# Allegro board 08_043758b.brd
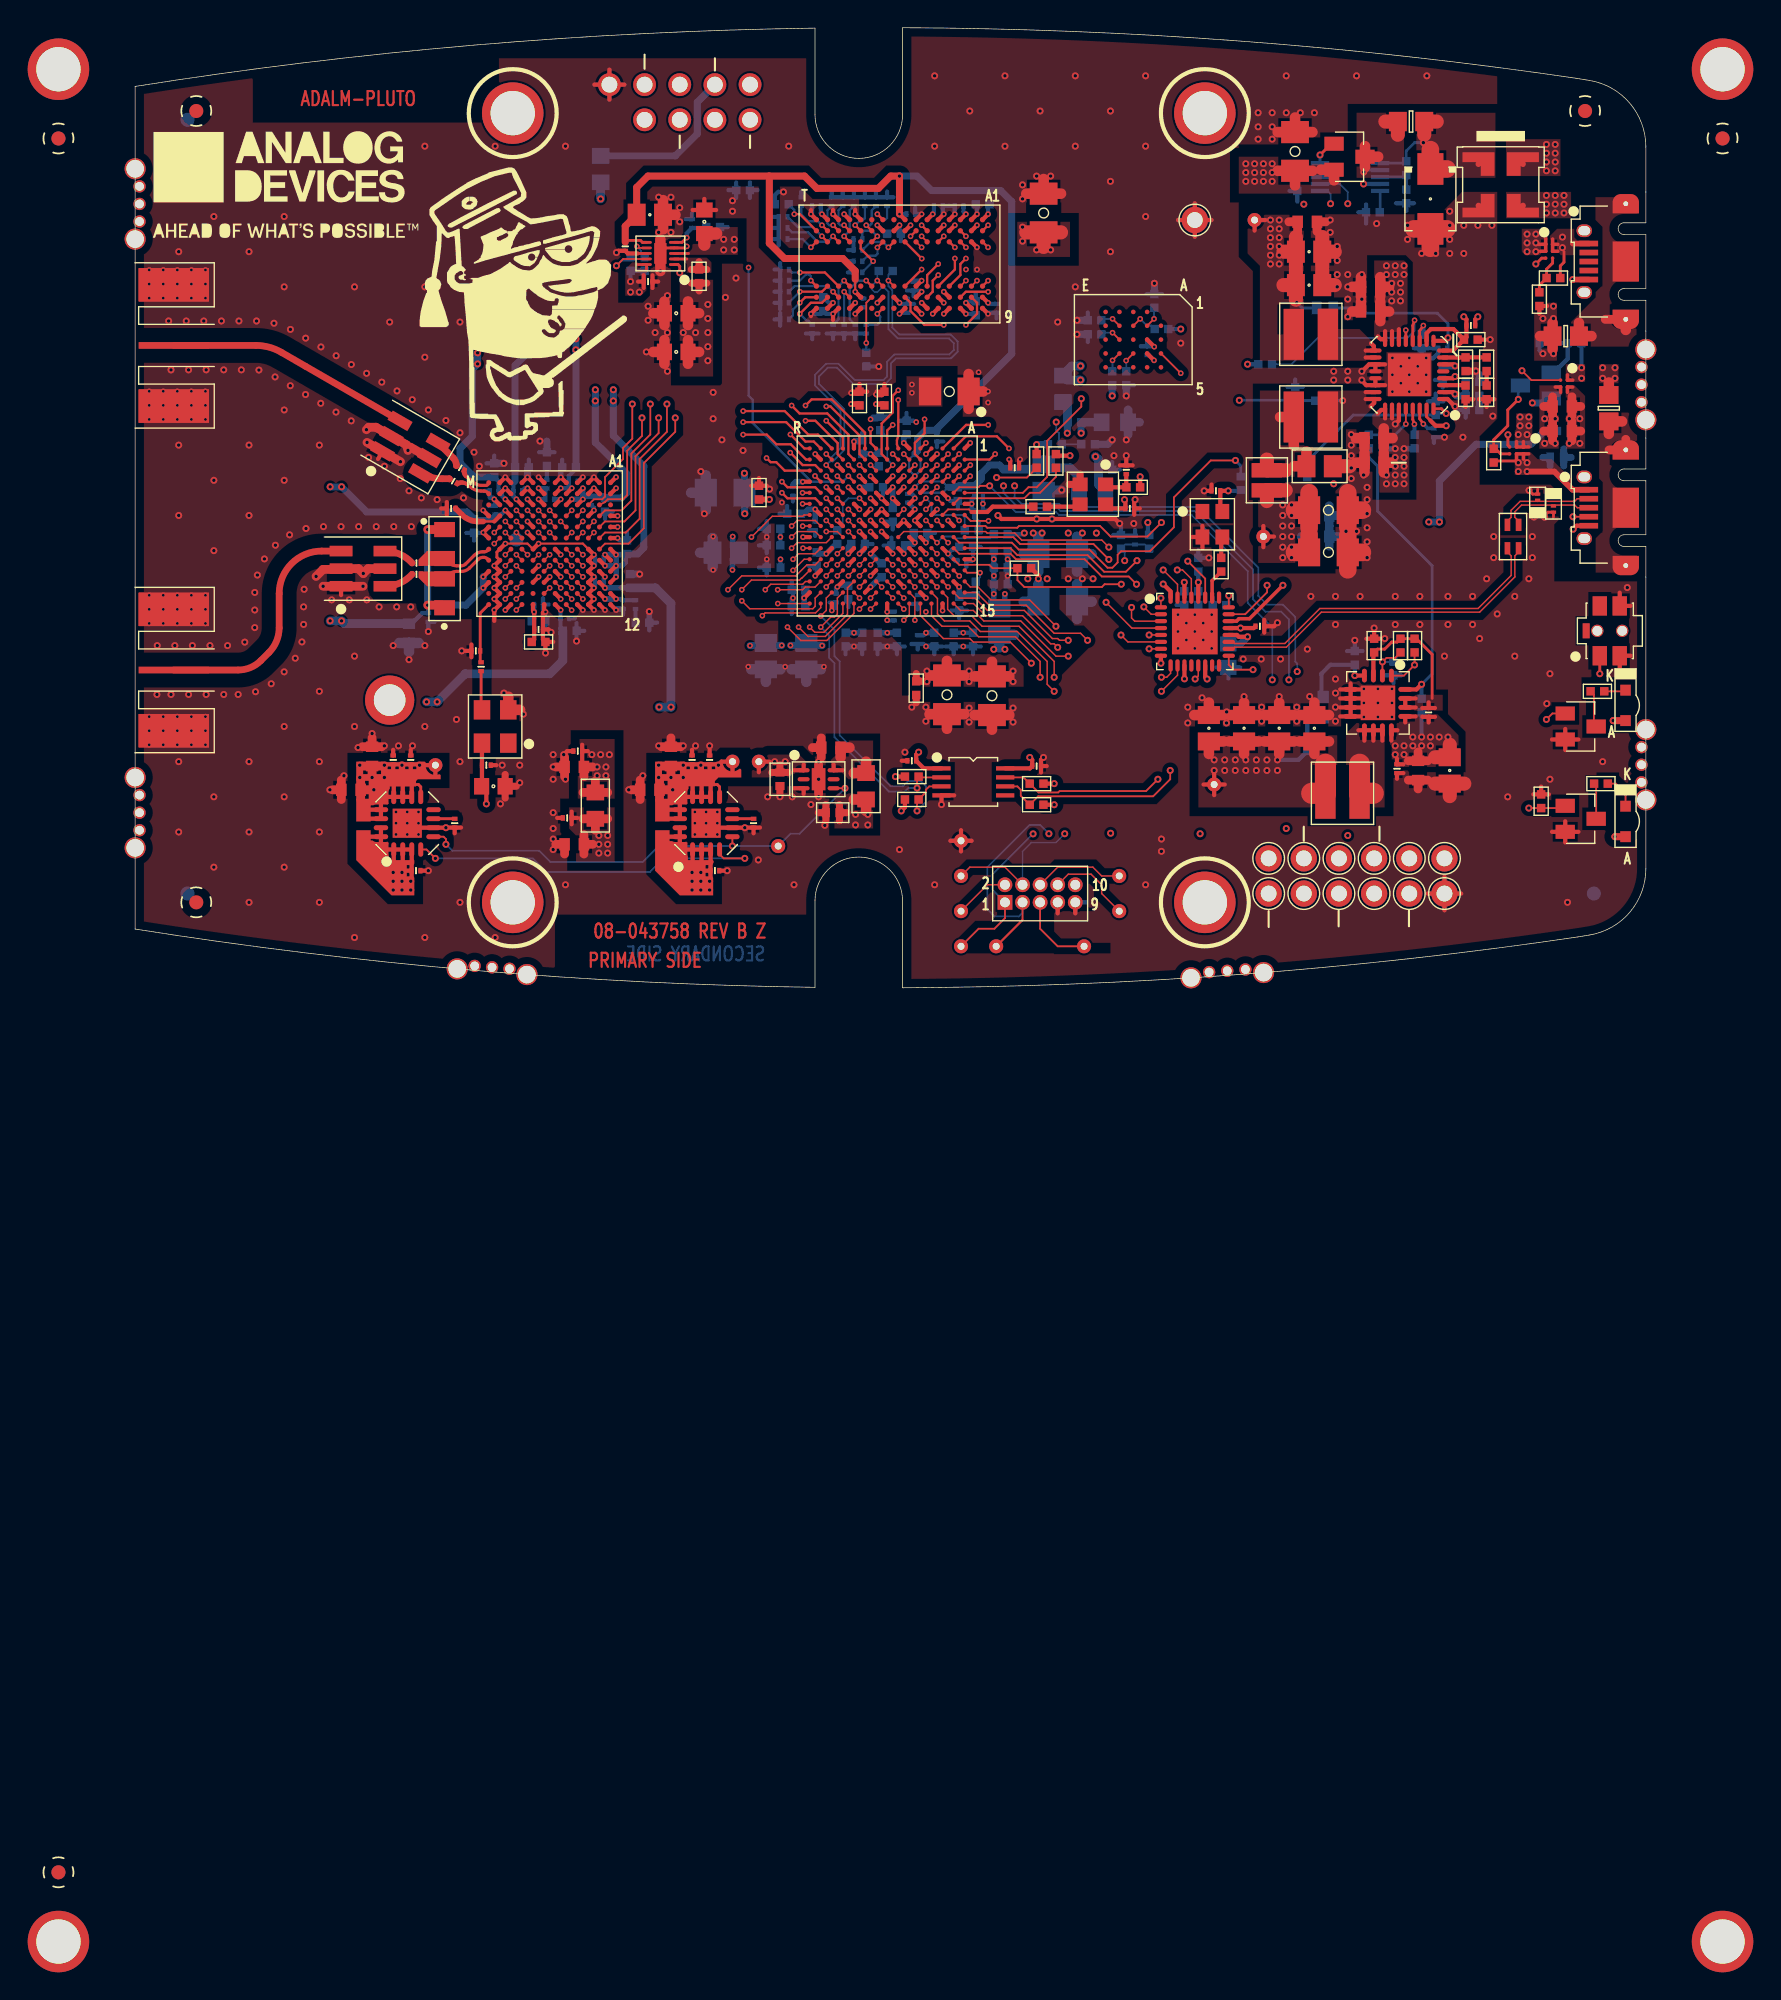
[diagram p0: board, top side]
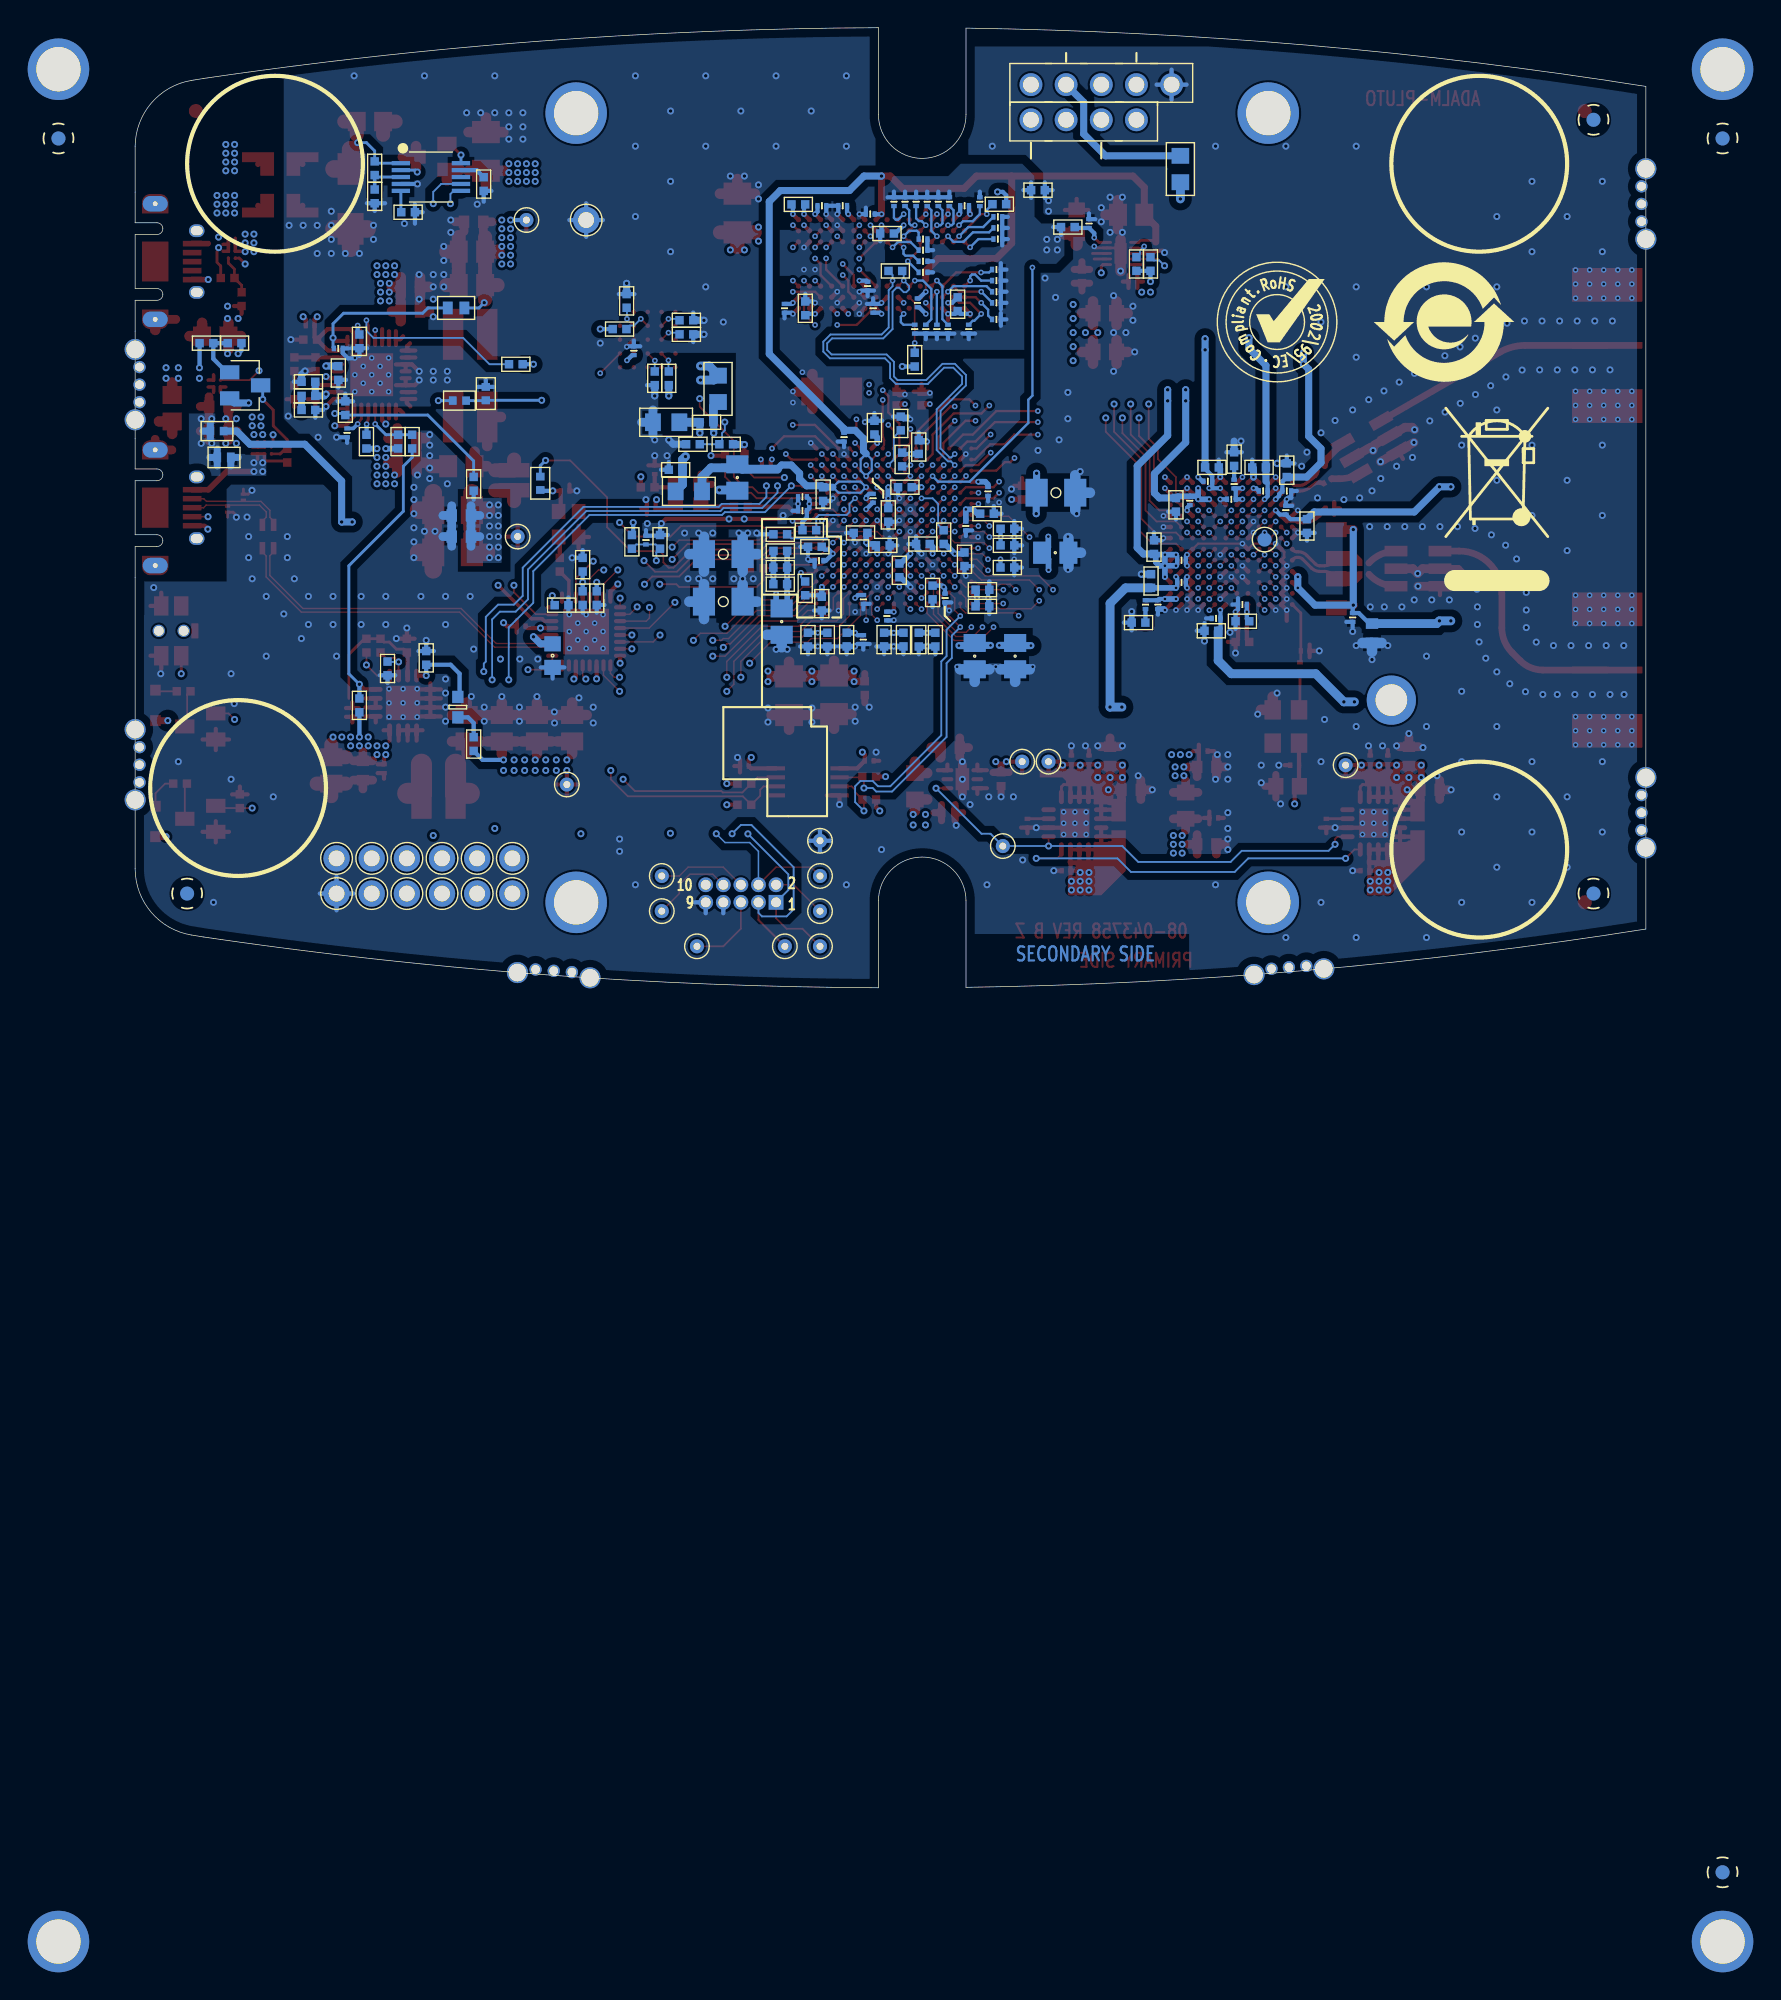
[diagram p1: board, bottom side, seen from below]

Outline 109.14 x 69.34 mm; copper layers: TOP, L2_GND, L3_PWR, L4_GND, L5_SIG, L6_SIG, L7_GND, L8_PWR, L9_GND, BOTTOM. Coordinates in mm from the lower left corner of the outline.
Outline path: 0,65.1 arc(24.48,68.08) 49.11,69.31 49.11,63.06 arc(52.28,59.9) 55.44,63.06 55.44,69.34 arc(79.87,68.37) 104.18,65.67 105.05,65.53 arc(107.98,63.88) 109.14,60.73 109.14,57.47 109.14,55.25 107.56,55.25 arc(107.26,55.12) 107.14,54.82 arc(107.26,54.52) 107.56,54.4 109.14,54.4 109.14,50.5 107.56,50.5 arc(107.26,50.37) 107.14,50.07 arc(107.26,49.77) 107.56,49.65 109.14,49.65 109.14,37.47 107.56,37.47 arc(107.26,37.34) 107.14,37.04 arc(107.26,36.74) 107.56,36.62 109.14,36.62 109.14,32.72 107.56,32.72 arc(107.26,32.59) 107.14,32.29 arc(107.26,31.99) 107.56,31.87 109.14,31.87 109.14,29.65 109.14,8.61 arc(107.98,5.45) 105.05,3.81 104.18,3.67 arc(79.87,0.97) 55.44,0 55.44,6.28 arc(52.28,9.44) 49.11,6.28 49.11,0.03 arc(24.48,1.26) 0,4.24 0,65.1

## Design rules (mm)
constraint set DEFAULT: min track width 0.127
net group DDR3_CK: nets DDR3_CK_N DDR3_CK_P
net group DDR3_DQS0: nets DDR3_DQS0_N DDR3_DQS0_P
net group DDR3_DQS1: nets DDR3_DQS1_N DDR3_DQS1_P
net group DP1: nets UNNAMED_9_CHOKE4P_I327_N2 UNNAMED_9_CHOKE4P_I327_N3
net group RX1A: nets RX1A_N RX1A_P
net group TX1A: nets TX1A_N TX1A_P
net group UART: nets UART_RX UART_TX
net group USB_OTG: nets USB_OTG_N USB_OTG_P
net group CTRL_IN: nets CTRL_IN0 CTRL_IN1 CTRL_IN2 CTRL_IN3
net group CTRL_OUT: nets IO_L08_34_CTRL_OUT0 IO_L08_34_CTRL_OUT1 IO_L13_34_CTRL_OUT2 IO_L13_34_CTRL_OUT3 IO_L21_34_CTRL_OUT4 IO_L21_34_CTRL_OUT5 IO_L22_34_CTRL_OUT6 IO_L22_34_CTRL_OUT7
net group JTAG: nets JTAG_TCK JTAG_TDI JTAG_TDO JTAG_TMS
net group PWR: nets VCCPLL VDD33_USB VDDA1P1_RX_VCO VTTVREF
net group QSPI: nets PS_MIO01_500_QSPI0_SS_B PS_MIO02_500_QSPI0_IO0 PS_MIO03_500_QSPI0_IO1 PS_MIO04_500_QSPI0_IO2 PS_MIO05_500_QSPI0_IO3 PS_MIO06_500_QSPI0_SCLK
net group RF: nets UNNAMED_7_CAP_I39_N2 UNNAMED_7_CAP_I40_N2 UNNAMED_7_CAP_I51_N1 UNNAMED_7_CAP_I52_N1 UNNAMED_7_CNBNC5P_I57_CNTR UNNAMED_7_CNBNC5P_I58_CNTR
net group RX: nets IO_L01_34_RX_D0 IO_L01_34_RX_D1 IO_L02_34_RX_D2 IO_L02_34_RX_D3 IO_L03_34_RX_D4 IO_L03_34_RX_D5 IO_L04_34_RX_D6 IO_L04_34_RX_D7 IO_L05_34_RX_D8 IO_L05_34_RX_D9 IO_L06_34_RX_D10 IO_L06_34_RX_D11 IO_L07_34_RX_FRAME IO_L12_MRCC_34_DATA_CLK
net group SPI: nets IO_L23_35_SPI_CLK IO_L23_35_SPI_ENB IO_L24_35_SPI_DI IO_L24_35_SPI_DO
net group TX: nets IO_L01_34_FB_CLK IO_L09_34_TX_FRAME IO_L15_34_TX_D0 IO_L15_34_TX_D1 IO_L16_34_TX_D2 IO_L16_34_TX_D3 IO_L17_34_TX_D4 IO_L17_34_TX_D5 IO_L18_34_TX_D6 IO_L18_34_TX_D7 IO_L19_34_TX_D8 IO_L19_34_TX_D9 IO_L20_34_TX_D10 IO_L20_34_TX_D11
net group USB_ULPI: nets PS_MIO28_501_USB0_D4 PS_MIO29_501_USB0_DIR PS_MIO30_501_USB0_STP PS_MIO31_501_USB0_NXT PS_MIO32_501_USB0_D0 PS_MIO33_501_USB0_D1 PS_MIO34_501_USB0_D2 PS_MIO35_501_USB0_D3 PS_MIO36_501_USB0_CLK PS_MIO37_501_USB0_D5 PS_MIO38_501_USB0_D6 PS_MIO39_501_USB0_D7

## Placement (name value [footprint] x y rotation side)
AD9361_CLKOUT  TESTPAD  [TPSMC40]  27.55 32.37 180 bottom
ADC  613 001 111 21  [CNHDR1X1H344]  44.42 65.22 180 bottom
C1  0.1uF  [C0201]  20.29 8.46 0 top
C2  0.01uF  [C0201]  23.09 11.88 270 top
C3  10uF  [C0603]  15.59 14.3 180 top
C4  10uF  [C0603]  17.12 16.71 90 top
C5  0.1uF  [C0201]  18.64 16.46 90 top
C6  0.1uF  [C0201]  19.91 16.46 90 top
C7  0.1uF  [C0201]  93.83 40.08 90 bottom
C8  0.1uF  [C0201]  91.16 15.82 270 top
C9  10uF  [C0603]  92.68 15.69 270 top
C10  0.1uF  [C0201]  41.88 8.46 0 top
C11  47uF  [C0805H60]  94.97 15.69 270 top
C12  0.01uF  [C0201]  44.68 11.88 270 top
C13  0.1uF  [C0201#2]  89.51 24.71 90 top
C14  10uF  [C0603]  38.71 16.71 90 top
C15  10uF  [C0603]  37.18 14.3 180 top
C16  0.1uF  [C0201]  40.23 16.46 90 top
C17  47uF  [C0805H60]  82.65 18.74 90 top
C18  0.1uF  [C0201]  41.5 16.46 90 top
C19  47uF  [C0805H60]  77.57 18.74 90 top
C20  47uF  [C0805H60]  80.11 18.74 90 top
C21  47uF  [C0805H60]  85.19 18.74 90 top
C22  10uF  [C0603]  31.72 10.36 180 top
C23  0.01uF  [C0201]  31.65 36.58 0 bottom
C24  0.01uF  [C0201]  25.94 35.88 180 bottom
C25  0.1uF  [C0201]  31.21 12.27 180 top
C26  0.01uF  [C0201]  31.05 26.68 0 bottom
C27  0.01uF  [C0201]  33.54 30.88 180 bottom
C28  1uF  [C0402]  31.35 37.58 180 bottom
C29  1uF  [C0402]  25.94 37.38 90 bottom
C30  1uF  [C0402]  31.39 25.78 0 bottom
C31  1uF  [C0402]  35.53 31.82 90 bottom
C32  10uF  [C0603]  31.72 15.95 180 top
C33  0.1uF  [C0201]  31.98 17.09 180 top
C34  1uF  [C0402]  27.94 37.58 0 bottom
C35  1uF  [C0402]  35.75 29.38 90 bottom
C36  1uF  [C0402]  24.48 33.35 270 bottom
C37  1uF  [C0402]  33.95 34.88 270 bottom
C38  1uF  [C0402]  29.15 26.47 0 bottom
C39  0.01uF  [C0201]  27.64 35.88 0 bottom
C40  0.01uF  [C0201]  33.54 29.28 180 bottom
C41  0.01uF  [C0201]  26.01 34.49 90 bottom
C42  0.01uF  [C0201]  32.95 35.18 270 bottom
C43  0.01uF  [C0201]  29.14 25.88 0 top
C44  0.01uF  [C0201]  29.15 27.68 0 bottom
C45  1uF  [C0402]  29.14 24.98 0 top
C46  0.1uF  [C0201]  71.85 34.62 0 top
C47  0.1uF  [C0201]  72.24 32.33 90 bottom
C48  0.1uF  [C0201]  73.11 46.01 90 bottom
C49  100uF  [C1206H71]  66.65 31.32 0 bottom
C50  4.7uF  [C0402]  62.53 31.55 0 bottom
C51  0.47uF  [C0402]  47.6 34.24 180 bottom
C52  0.1uF  [C0201]  60.93 35.45 0 bottom
C53  0.01uF  [C0201]  60.93 34.45 0 bottom
C54  100uF  [C1206H71]  58.82 43.06 0 top
C55  4.7uF  [C0402]  55.73 40.45 90 bottom
C56  0.47uF  [C0402]  45.07 35.76 90 top
C57  0.47uF  [C0402]  54.13 42.55 90 top
C58  0.47uF  [C0402]  52.33 42.55 90 top
C59  0.47uF  [C0402]  52.53 39.05 90 bottom
C60  0.1uF  [C0201]  63.54 37.56 0 top
C61  0.01uF  [C0201]  47.52 35.85 270 bottom
C62  0.01uF  [C0201]  37.06 51 180 top
C63  0.01uF  [C0201]  56.03 55.88 180 bottom
C64  100uF  [C1206H71]  61.9 21.09 270 top
C65  47uF  [C0805H60]  48.49 23.95 270 bottom
C66  4.7uF  [C0402]  53.93 30.15 270 bottom
C67  4.7uF  [C0402]  52.53 25.14 270 bottom
C68  0.47uF  [C0402]  56.43 21.64 270 top
C69  0.47uF  [C0402]  60.03 31.85 0 bottom
C70  0.47uF  [C0402]  54.73 34.15 270 bottom
C71  100uF  [C1206H71]  58.65 21.16 270 top
C72  0.47uF  [C0402]  52.23 32.05 0 bottom
C73  4.7uF  [C0402]  53.53 36.15 0 bottom
C74  0.47uF  [C0402]  55.13 31.95 180 bottom
C75  0.47uF  [C0402]  56.73 32.85 0 bottom
C76  100uF  [C1206H71]  42.62 35.75 180 bottom
C77  47uF  [C0805H60]  42.67 31.42 180 bottom
C78  4.7uF  [C0402]  46.12 31.95 180 bottom
C79  10uF  [C0603#2]  41.12 55.32 90 top
C80  0.01uF  [C0201]  40.23 55.19 90 bottom
C81  0.22UF  [C0805]  37.18 55.83 0 top
C82  10uF  [C0603#2]  39.09 45.92 180 top
C83  10uF  [C0603#2]  39.09 48.71 180 top
C84  0.01uF  [C0201]  35.41 53.54 270 top
C85  47uF  [C0805H60]  65.64 36.85 270 bottom
C86  4.7uF  [C0402]  49.72 49.37 270 bottom
C87  4.7uF  [C0402]  60.73 49.07 90 bottom
C88  0.47uF  [C0402]  61.23 56.58 180 bottom
C89  0.47uF  [C0402]  54.82 54.47 0 bottom
C90  0.47uF  [C0402]  46.12 33.15 180 bottom
C91  0.1uF  [C0201]  55.82 49.07 90 bottom
C92  0.1uF  [C0201]  56.22 50.67 270 bottom
C93  0.47uF  [C0402]  67.86 40.84 0 bottom
C94  0.1uF  [C0201]  59.52 56.48 180 bottom
C95  0.1uF  [C0201]  58.02 56.48 0 bottom
C96  0.1uF  [C0201]  49.22 56.47 180 bottom
C97  0.1uF  [C0201]  62.23 49.07 270 bottom
C98  0.1uF  [C0201]  55.83 35.35 90 bottom
C99  0.01uF  [C0201]  57.92 39.76 90 bottom
C100  100uF  [C1206H71]  65.63 55.95 90 top
C101  4.7uF  [C0402]  43.91 57.6 180 bottom
C102  0.01uF  [C0201]  52.62 49.47 270 bottom
C103  47uF  [C0805H60]  62.43 26.44 270 bottom
C104  47uF  [C0805H60]  45.57 23.95 270 bottom
C105  4.7uF  [C0402]  55.03 25.14 270 bottom
C106  4.7uF  [C0402]  51.33 25.14 270 bottom
C107  4.7uF  [C0402]  60.53 25.14 270 bottom
C108  4.7uF  [C0402]  46.13 30.35 180 bottom
C109  0.47uF  [C0402]  53.63 25.14 270 bottom
C110  0.47uF  [C0402]  51.53 28.55 270 bottom
C111  0.47uF  [C0402]  59.53 27.74 270 bottom
C112  0.47uF  [C0402]  47.93 28.75 180 bottom
C113  0.47uF  [C0402]  59.13 25.14 270 bottom
C114  0.47uF  [C0402]  47.93 27.55 180 bottom
C115  0.47uF  [C0402]  57.74 25.14 270 bottom
C116  0.47uF  [C0402]  49.22 30.95 270 bottom
C117  0.1uF  [C0201]  56.53 25.14 270 bottom
C118  0.1uF  [C0201]  50.63 28.15 270 bottom
C119  0.01uF  [C0201]  54.83 26.85 270 bottom
C120  0.01uF  [C0201]  49.13 33.35 270 bottom
C121  10uF  [C0603#2]  25.88 14.55 0 top
C122  0.1uF  [C0201]  25.37 16.08 0 top
C123  18pF  [C0201]  24.99 23.19 90 top
C124  18pF  [C0201]  24.61 24.33 180 top
C125  0.001uF  [C0201]  29.94 35.28 180 bottom
C126  1uF  [C0402]  29.74 38.18 270 bottom
C127  1uF  [C0402]  36.65 26.37 0 bottom
C128  0.001uF  [C0201]  35.25 27.67 270 bottom
C129  0.001uF  [C0201]  21.18 26.74 90 bottom
C130  10uF  [C0603]  19.78 25.6 270 bottom
C131  18pF  [C0201]  20.32 29.86 180 top
C132  18pF  [C0201]  20.32 30.67 180 top
C133  18pF  [C0201]  22.98 36.59 330 top
C134  18pF  [C0201]  23.49 37.55 330 top
C135  10uF  [C0603]  89.51 39.7 180 top
C136  10uF  [C0603]  89.25 48.84 180 top
C137  10uF  [C0603]  89.51 37.92 180 top
C138  10uF  [C0603]  89.25 50.62 180 top
C139  0.047uF  [C0402]  92.94 46.68 90 bottom
C140  1uF  [C0402]  76.81 30.55 90 bottom
C141  1uF  [C0402]  96.49 46.81 0 top
C142  150pF  [C0402]  96.62 43.76 180 bottom
C143  180pF  [C0402]  96.11 45.03 90 top
C144  0.0033uF  [C0402]  97.64 45.03 270 top
C145  47uF  [C0805H60]  84.81 53.16 0 top
C146  22uF  [C0805H53]  85.57 37.67 0 top
C147  0.0056uF  [C0402]  96.62 41.73 0 bottom
C148  47uF  [C0805H60]  84.81 50.75 0 top
C149  100uF  [C1206H71]  86.21 31.44 0 top
C150  100uF  [C1206H71]  86.21 34.49 0 top
C151  10uF  [C0603]  84.68 55.32 0 top
C152  10uF  [C0603]  85.57 34.11 0 bottom
C153  10uF  [C0603]  85.57 32.59 0 bottom
C154  1uF  [C0402]  75.79 28.14 270 bottom
C155  0.047uF  [C0402]  83.96 58.04 270 bottom
C156  0.47uF  [C0402]  89.42 56.01 180 bottom
C157  100uF  [C1206H71]  83.79 60.4 90 top
C158  100uF  [C1206H71]  66.65 27.89 0 bottom
C159  4.7uF  [C0402]  62.53 30.35 0 bottom
C160  0.47uF  [C0402]  62.53 29.15 0 bottom
C161  0.1uF  [C0201]  56.53 28.05 270 bottom
C162  0.01uF  [C0201]  59.73 30.85 0 bottom
C163  0.1uF  [C0201]  78.08 35.89 0 top
C164  0.1uF  [C0201]  81.25 26.11 0 top
C165  2.2uF  [C0603#2]  78.98 23.99 270 bottom
C166  0.1uF  [C0201]  56.11 16.39 0 top
C167  0.1uF  [C0201]  65.12 16.01 0 top
C168  1uF  [C0402]  76.81 28.14 270 bottom
C169  1uF  [C0402]  50.39 12.65 180 top
C170  1uF  [C0402]  46.58 15.06 270 top
C171  2.2uF  [C0603]  103.1 41.98 180 top
C172  2.2uF  [C0603]  103.1 40.21 180 top
C173  10uF  [C0603]  50.26 17.35 180 top
C174  4.7uF  [C0402]  70.09 37.41 0 bottom
C178  0.47uF  [C0402]  59.44 35.65 270 bottom
D1  SESD0201X1UN-0020-09  [D0201]  102.46 34.57 270 top
D2  SESD0201X1UN-0020-09  [D0201]  101.32 35.43 90 top
D3  SMAJ5A  [DIOSMJ5_0]  93.57 56.97 270 top
DAC1  613 001 111 21  [CNHDR1X1H344]  36.8 65.22 180 bottom
DAC2  613 001 111 21  [CNHDR1X1H344]  36.8 62.68 180 bottom
DS1  LTST-S220TBKT  [LED0804]  107.67 20.39 270 top
DS2  LTST-S220TBKT  [LED0804]  107.67 12.01 270 top
E1  100OHM  [L0805]  69.14 35.85 180 bottom
E2  100OHM  [L0805]  52.8 14.55 90 top
E3  100OHM  [L0805]  33.63 59.13 270 bottom
E4  100OHM  [L0805]  33.25 13.15 90 top
E5  100OHM  [L0805]  67.03 43.25 270 bottom
E6  100OHM  [L0805]  70.78 40.84 180 bottom
F1  0.5A  [F0402H20]  102.72 38.3 180 bottom
GND  WP45  [unnamed#3]  94.59 6.8 180 bottom
GND#2  WP45  [unnamed#3]  76.55 55.45 180 bottom
GND#3  613 001 111 21  [unnamed#3]  34.26 65.22 180 bottom
GND#4  TESTPAD  [unnamed#3]  59.66 10.61 180 bottom
GPO0  613 001 111 21  [CNHDR1X1H344]  44.42 62.68 180 bottom
GPO1  613 001 111 21  [CNHDR1X1H344]  41.88 62.68 180 bottom
GPO2  613 001 111 21  [CNHDR1X1H344]  39.34 62.68 180 bottom
GPO3  613 001 111 21  [CNHDR1X1H344]  39.34 65.22 180 bottom
JTAG_BOOT  TESTPAD  [TPSMC40]  68.55 2.99 180 bottom
L2  1.5uH  [LSMSQ157H83]  84.94 47.19 180 top
L3  1.5uH  [LSMSQ157H83]  84.94 41.22 180 top
L4  1uH  [LSMSQ157H83]  87.22 14.04 180 top
L5  270NH  [LSMSQ79H41]  81.76 36.65 270 top
L6  90OHMS AT 100MEGHZ  [L0805-4PH39]  99.54 32.59 90 top
L7  800OHMS AT 100MEGHZ  [L2020_A]  98.65 57.99 180 top
L8  330NH  [L0805-F]  22.36 28.49 90 top
L9  330NH  [L0805-F]  22.36 32.05 270 top
L10P  WP45  [TPC75D45]  81.89 6.8 180 bottom
L12N  WP45  [TPC75D45]  84.43 6.8 180 bottom
L24N  WP45  [TPC75D45]  81.89 9.34 180 bottom
MIO0  WP45  [TPC75D45]  92.05 9.34 180 bottom
MIO09  WP45  [TPC75D45]  89.51 6.8 180 bottom
MIO10  WP45  [TPC75D45]  92.05 6.8 180 bottom
MIO11  WP45  [TPC75D45]  89.51 9.34 180 bottom
MIO48  WP45  [TPC75D45]  84.43 9.34 180 bottom
MIO49  WP45  [TPC75D45]  86.97 6.8 180 bottom
MIO53  WP45  [TPC75D45]  86.97 9.34 180 bottom
NOREF  -  [unnamed]  -5.54 61.34 0 top
NOREF#2  -  [#2]  -8.54 69.34 0 top
NOREF#3  -  [#2]  115.99 67.29 0 top
NOREF#4  -  [unnamed]  4.42 63.32 0 top
NOREF#5  -  [unnamed]  0 15.18 0 top
NOREF#6  -  [#2]  -8.54 -71.88 0 top
NOREF#7  -  [#2]  -1.27 -61.78 0 top
NOREF#8  -  [unnamed]  81.52 1.1 0 top
NOREF#9  -  [unnamed]  109.14 18.65 0 top
NOREF#10  -  [unnamed]  104.75 63.32 0 top
NOREF#11  -  [#2]  -1.27 59.15 0 top
NOREF#12  -  [unnamed]  77.28 6.17 180 top
NOREF#13  -  [#2]  -8.54 69.34 0 top
NOREF#14  -  [unnamed]  0.32 57.88 0 top
NOREF#15  -  [unnamed]  18.39 20.77 0 top
NOREF#16  -  [unnamed]  27.04 1.37 0 top
NOREF#17  -  [unnamed]  0 59.15 0 top
NOREF#18  -  [unnamed]  77.28 63.17 180 top
NOREF#19  -  [#2]  114.68 -68.88 0 top
NOREF#20  -  [unnamed]  24.53 1.58 0 top
NOREF#21  -  [#2]  10.89 57.99 0 top
NOREF#22  -  [#2]  -5.54 66.34 0 top
NOREF#23  -  [unnamed]  76.28 0.72 0 top
NOREF#24  -  [unnamed]  108.82 42.29 0 top
NOREF#25  -  [#2]  11.73 -2.58 0 top
NOREF#26  -  [#2]  -99.72 -146.23 0 top
NOREF#27  -  [unnamed]  114.68 61.34 0 top
NOREF#28  -  [unnamed]  114.68 66.34 180 top
NOREF#29  -  [unnamed]  25.79 1.48 0 top
NOREF#30  -  [unnamed]  0 54.07 0 top
NOREF#31  -  [unnamed]  78.9 1.23 0 top
NOREF#32  -  [#2]  95.96 -2.55 0 top
NOREF#33  -  [#2]  -2.54 -71.88 0 top
NOREF#34  -  [unnamed]  108.82 14.84 0 top
NOREF#35  -  [#2]  202.3 71.42 0 top
NOREF#36  -  [#2]  -8.54 -71.88 0 top
NOREF#37  -  [#2]  -99.72 -146.23 0 top
NOREF#38  -  [unnamed]  114.68 -68.88 180 top
NOREF#39  -  [unnamed]  27.28 63.17 180 top
NOREF#40  -  [unnamed]  109.14 46.1 0 top
NOREF#41  -  [#2]  117.68 -71.88 0 top
NOREF#42  -  [#2]  -1.27 -56.7 0 top
NOREF#43  -  [unnamed]  0.32 11.37 0 top
NOREF#44  -  [unnamed]  108.82 17.38 0 top
NOREF#45  -  [#2]  -1.27 54.07 0 top
NOREF#46  -  [unnamed]  109.14 13.57 0 top
NOREF#47  -  [unnamed]  0.32 55.34 0 top
NOREF#48  -  [#2]  -1.27 10.1 0 top
NOREF#49  -  [unnamed]  0.32 56.61 0 top
NOREF#50  -  [unnamed]  109.14 41.02 0 top
NOREF#51  -  [#2]  117.68 -71.88 90 top
NOREF#52  -  [#2]  -99.72 -146.23 0 top
NOREF#53  -  [#2]  111.68 -71.88 0 top
NOREF#54  -  [#2]  28.04 49.35 0 top
NOREF#55  -  [#2]  -5.54 -68.88 0 top
NOREF#56  -  [unnamed]  0.32 12.64 0 top
NOREF#57  -  [#2]  -37.76 235.07 0 top
NOREF#58  -  [#2]  -1.27 -12.73 0 top
NOREF#59  -  [unnamed]  23.27 1.36 0 top
NOREF#60  -  [unnamed]  108.82 44.83 0 top
NOREF#61  -  [unnamed]  80.21 1.32 0 top
NOREF#62  -  [unnamed]  77.59 1.13 0 top
NOREF#63  -  [#2]  -5.54 -68.88 0 top
NOREF#64  -  [unnamed]  108.82 16.11 0 top
NOREF#65  -  [unnamed]  27.28 6.17 180 top
NOREF#66  -  [#2]  109.14 -63.28 0 top
NOREF#67  -  [unnamed]  4.42 6.17 0 top
NOREF#68  -  [unnamed]  28.3 0.95 0 top
NOREF#69  -  [#2]  115.67 61.49 0 top
NOREF#70  -  [unnamed]  108.82 43.56 0 top
NOREF#71  -  [#2]  0 -67.64 0 top
NOREF#72  -  [#2]  -1.27 -17.81 0 top
NOREF#73  -  [unnamed]  0.32 13.91 0 top
NOREF#74  -  [unnamed]  -5.54 66.34 180 top
NOREF#75  -  [#2]  -1.27 15.18 0 top
NOREF#76  -  [unnamed]  -5.54 -68.88 180 top
NOREF#77  -  [unnamed]  0 10.1 0 top
NOREF#78  -  [#2]  -88.72 16.63 0 top
NOREF#79  -  [unnamed]  -5.54 -63.88 0 top
NOREF#80  -  [#2]  394.55 166.11 0 top
NOREF#81  -  [#2]  1.5 45.54 180 bottom
NOREF#82  -  [unnamed]  114.68 61.34 180 bottom
NOREF#83  -  [unnamed]  3.78 6.8 180 bottom
NOREF#84  -  [#2]  14.58 48.08 180 bottom
NOREF#85  -  [#2]  26.64 48.08 180 bottom
NOREF#86  -  [unnamed]  -5.54 61.34 180 bottom
NOREF#87  -  [unnamed]  -5.54 -63.88 180 bottom
NOREF#88  -  [unnamed]  3.78 62.68 180 bottom
NOREF#89  -  [unnamed]  105.38 6.8 180 bottom
P1  FTSH-105-01-L-D  [CNHDR2X5H219]  62.84 6.17 0 top
P2  47590-0001  [CNMOLEX47590-0001]  109.14 34.67 180 top
P3  47590-0001  [CNMOLEX47590-0001]  109.14 52.45 180 top
PG_1P3V  TESTPAD  [TPSMC40]  46.45 10.23 180 bottom
Q1  BSS138LT1G  [SOT23]  104.43 18.87 270 top
Q2  BSS138LT1G  [SOT23]  101.19 43.51 270 bottom
Q3  SI2304DDS-T1-GE3  [SOT23]  87.73 60.02 270 top
Q4  BSS138LT1G  [SOT23]  104.43 12.2 270 top
R1  10  [R0201]  93.44 19.89 270 top
R2  27.4K  [R0402]  88.11 23.82 270 bottom
R3  46.4K  [R0402]  90.9 23.06 90 bottom
R4  17.8K  [R0603]  85.82 20.27 270 bottom
R5  0  [R0402]  92.43 24.71 270 top
R6  10K  [R0402]  92.94 20.39 90 bottom
R7  1K  [R0402]  84.68 17.6 270 bottom
R8  10K  [R0402]  72.11 36.14 180 top
R9  10K  [R0201]  71.6 37.41 90 top
R10  0  [R0402]  91.41 24.71 270 top
R11  4.7K  [R0402]  66.44 39.25 0 bottom
R12  39  [R0402]  65.38 34.74 180 top
R13  20K  [R0402]  73.25 32.2 270 bottom
R14  240  [R0402]  74.14 47.57 180 bottom
R15  0  [R0402]  71.22 32.2 90 bottom
R16  120  [R0201]  51.92 56.77 90 bottom
R17  120  [R0201]  46.82 54.88 180 bottom
R18  120  [R0201]  46.91 50.27 180 bottom
R19  120  [R0201]  48.92 47.57 270 bottom
R20  120  [R0201]  46.92 48.27 180 bottom
R21  120  [R0201]  52.02 47.57 270 bottom
R22  120  [R0201]  46.92 51.87 180 bottom
R23  120  [R0201]  51.12 56.77 90 bottom
R24  120  [R0201]  50.32 56.77 90 bottom
R25  120  [R0201]  48.12 56.77 90 bottom
R26  120  [R0201]  46.82 55.68 180 bottom
R27  120  [R0201]  46.91 49.47 180 bottom
R28  120  [R0201]  50.42 47.57 270 bottom
R29  120  [R0201]  46.92 51.07 180 bottom
R30  120  [R0201]  51.22 47.57 270 bottom
R31  120  [R0201]  52.22 54.07 180 bottom
R32  120  [R0201]  52.22 52.47 180 bottom
R33  120  [R0201]  54.32 56.77 90 bottom
R34  120  [R0201]  46.82 54.07 180 bottom
R35  120  [R0201]  52.72 56.77 90 bottom
R36  120  [R0201]  52.22 51.67 180 bottom
R37  120  [R0201]  52.22 53.27 180 bottom
R38  120  [R0201]  52.82 47.57 270 bottom
R39  120  [R0201]  53.52 56.77 90 bottom
R40  240  [R0402]  53.83 40.75 90 bottom
R41  240  [R0402]  53.73 38.15 90 bottom
R42  1K  [R0402]  46.71 56.59 180 bottom
R43  0  [R0402]  41.76 54.94 180 bottom
R44  0  [R0402]  40.74 51.38 90 top
R45  0  [R0402]  60.43 33.05 180 bottom
R46  4.7K  [R0402]  50.73 32.55 270 bottom
R47  4.7K  [R0402]  65.12 38.05 90 top
R48  470  [R0402]  105.64 21.41 180 top
R49  14.3K  [R0201]  22.83 34.62 0 top
R50  100K  [R0402]  81.63 45.03 180 bottom
R51  1  [R0201]  29.74 36.38 270 bottom
R52  1  [R0201]  36.15 27.67 270 bottom
R53  27.4K  [R0402]  96.11 43 90 top
R54  4.7K  [R0402]  94.46 44.4 270 bottom
R55  1K  [R0805]  106.46 41.86 90 top
R56  10  [R0201]  96.49 47.83 180 top
R57  20K  [R0402]  79.87 36.43 90 bottom
R58  1K  [R0805]  103.35 47.06 180 top
R59  100K  [R0402]  92.43 39.44 270 bottom
R60  10K  [R0402]  96.62 42.75 0 bottom
R61  10K  [R0402]  97.64 43 90 top
R62  17.8K  [R0603#2]  85.95 49.1 0 bottom
R63  14.3K  [R0201]  94.46 46.17 180 bottom
R64  46.4K  [R0402]  84.68 36.4 270 bottom
R65  23.2K  [R0402]  93.95 41.86 270 bottom
R66  240  [R0402]  103.99 46.56 180 bottom
R67  10K  [R0402]  101.95 46.56 180 bottom
R68  10K  [R0402]  102.46 51.25 180 top
R69  10K  [R0402]  101.45 49.73 270 top
R70  10K  [R0402]  98.14 38.43 90 top
R71  10K  [R0402]  91.83 59.19 270 bottom
R72  10K  [R0402]  91.83 57.15 270 bottom
R73  0.05  [R0805]  92.17 62.56 180 top
R74  10K  [R0402]  64.23 30.3 180 top
R75  10K  [R0402]  101.57 13.47 90 top
R76  20K  [R0402]  60.73 28.84 90 bottom
R77  8.06K  [R0402]  78.33 27.63 180 bottom
R78  4.7K  [R0402]  56.11 13.6 0 top
R79  4.7K  [R0402]  56.11 15.25 0 top
R80  4.7K  [R0402]  65.12 13.22 180 top
R81  4.7K  [R0402]  65.12 14.74 180 top
R82  39  [R0402]  78.46 30.55 90 top
R83  20K  [R0402]  62.53 32.75 180 bottom
R84  20K  [R0402]  66.52 38.05 90 top
R85  0  [R0402]  90.14 39.44 90 bottom
R86  0  [R0402]  89.13 39.44 90 bottom
R87  470  [R0402]  105.89 14.74 180 top
R88  1K  [R0402]  103.22 40.21 180 bottom
R89  4.7K  [R0402]  85.71 42.4 180 bottom
R90  1K  [R0402]  83.81 42.91 90 bottom
R91  4.7K  [R0402]  68.84 39.25 0 bottom
R116  20K  [R0402]  73.63 49.6 90 bottom
R119  20K  [R0402]  69.31 48.21 180 bottom
R120  20K  [R0402]  69.31 47.19 180 bottom
R121  20K  [R0402]  71.6 44.02 270 bottom
R122  20K  [R0402]  70.58 44.02 270 bottom
R142  80.6  [R0402]  54.22 51.77 180 bottom
R165  240  [R0402]  52.82 45.36 270 bottom
R221  10K  [R0402]  35.79 52.27 90 bottom
R222  10K  [R0402]  36.8 52.27 90 bottom
RX  TESTPAD  [TPSMC40]  59.66 2.99 180 bottom
RX1A  JCCEM001  [CNSMARAL687W375H171]  2.54 46.39 180 top
S1  PTS840 GKP SMTR LFS  [SWSML140W138H55]  106.53 25.78 0 top
T1  TCM1-63AX+  [TSML150W160H160]  19.88 39.05 60 top
T5  TCM1-63AX+  [TSML150W160H160]  16.46 30.27 90 top
TCK  TESTPAD  [TPSMC40]  59.66 8.07 180 bottom
TDI  TESTPAD  [TPSMC40]  71.09 5.53 180 bottom
TDO  TESTPAD  [TPSMC40]  71.09 8.07 180 bottom
TMS  TESTPAD  [TPSMC40]  59.66 5.53 180 bottom
TX  TESTPAD  [TPSMC40]  62.2 2.99 180 bottom
TX1A  JCCEM001  [CNSMARAL687W375H171]  2.54 22.95 180 top
U1  ADP1754ACPZ-1.3  [QFN16_4X4_PAD2_1X2_1]  19.66 11.88 0 top
U2  MT41K256M16TW-107 IT:P  [FBGA96_C]  55.22 52.27 180 top
U3  ADP2164ACPZ  [QFN16_4X4_PAD2_5X2_5]  89.78 20.57 180 top
U4  XC7Z010-1CLG225C  [CSPBGA225]  54.33 33.35 180 top
U5  AD9363ABCZ  [BGA144-2]  29.94 32.08 180 top
U6  ADP2114ACPZ  [QFN32_5X5_PAD3_1X3_1]  92.05 44.27 90 top
U7  ADP1754ACPZ-1.3  [QFN16_4X4_PAD2_1X2_1]  41.25 11.88 0 top
U8  NCP339AFCT2G  [WLCSP6]  102.15 53.19 270 top
U9  NCP339AFCT2G  [WLCSP6]  99.79 38.81 180 top
U10  ADM1177-1ARMZ  [RM10]  87.77 58.55 270 bottom
U11  TCA9517DGKR  [MSOP8]  60.55 14.87 270 top
U12  ADM7160ACPZN1.8  [DFN6_2X2_PAD1_6X1]  49.38 15.06 270 top
U13  MT25QU256ABA8E12-1SIT  [TBGA24]  72.11 46.81 180 top
U14  TPS51206DSQR  [SON10_2X2_PAD1_5X0_9]  37.95 53.03 90 top
U15  USB3320C-EZK  [QFN32_5X5_PAD3_3X3_3]  76.55 25.73 270 top
U16  ADP198ACBZ-11  [WLCSP4-2]  103.22 43.63 180 top
UNK1P0V  TESTPAD  [TPSMC40]  77.95 14.68 180 bottom
UNK1P3V_A  TESTPAD  [TPSMC40]  43.15 16.33 180 bottom
UNK1P3V_B  TESTPAD  [TPSMC40]  21.69 16.08 180 bottom
UNK1P8V_CLK  TESTPAD  [TPSMC40]  45.06 16.33 180 bottom
UNK1V8  TESTPAD  [TPSMC40]  81.51 32.59 180 bottom
UNK1V8#2  WP45  [TPSMC40]  94.59 9.34 180 bottom
UNK1V35  TESTPAD  [TPSMC40]  80.87 55.45 180 bottom
VDD_GPO  613 001 111 21  [CNHDR1X1H344]  41.88 65.22 180 bottom
Y1  24MEGHZ  [YSML98W79H35]  77.82 33.47 270 top
Y2  33.333MEGHZ  [YSML98W79H35]  69.19 35.63 180 top
Y3  40MEGHz  [YSML126W98H47]  26.01 18.87 90 top

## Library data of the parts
AD9361_CLKOUT JTAG_BOOT PG_1P3V RX TCK TDI TDO TMS TX UNK1P0V UNK1P3V_A UNK1P3V_B UNK1P8V_CLK UNK1V8 UNK1V35 = NCTESTPAD: Tolerance: N/A; User Part Number: UPN; alternate symbols: (); part number: NCTESTPAD_SM-TESTPAD,E019801,TPSMC40; tolerance: N/A
ADC DAC1 DAC2 GPO0-GPO3 VDD_GPO = CN1P: User Part Number: UPN; Tolerance: N/A; alternate symbols: (); part number: CN1P_TH-613 001 111 21,E016125,CNHDR1X1H344; tolerance: N/A
C1 C5-C8 C10 C16 C18 C25 C33 C46-C48 C52 C60 C91 C92 C94-C98 C117 C118 C122 C161 C163 C164 C166 C167 = CAP: User Part Number: UPN; Tolerance: 20; part number: CAP_SM-0.1UF,16V,20,E017331,C0201; tolerance: 20
C2 C12 C23 C24 C26 C27 C39-C44 C53 C61-C63 C80 C84 C99 C102 C119 C120 C162 = CAP: User Part Number: UPN; Tolerance: 10; part number: CAP_SM-0.01UF,10V,10,E007201,C0201; tolerance: 10
C3 C4 C9 C14 C15 C22 C32 C79 C82 C83 C121 C130 C135-C138 C151-C153 C173 = CAP: Tolerance: 20; User Part Number: UPN; alternate symbols: C0603L_ALT; part number: CAP_SM-10UF,6.3V,20,E007143,C0603; tolerance: 20
C11 C17 C19-C21 C65 C77 C85 C103 C104 C145 C148 = CAP: Tolerance: 20; User Part Number: UPN; alternate symbols: (); part number: CAP_SM-47UF,6.3V,20,E008247,C0805H60; tolerance: 20
C13 = CAP: Tolerance: 20; User Part Number: UPN; alternate symbols: C0402_ALT; part number: CAP_SM-0.1UF,16V,20,E017331,C0201; tolerance: 20
C28-C31 C34-C38 C45 C127 C140 C141 C154 C168 = CAP: Tolerance: 10; User Part Number: UPN; alternate symbols: C0402_ALT; part number: CAP_SM-1UF,6.3V,10,E007449,C0402; tolerance: 10
C49 C54 C64 C71 C76 C100 C149 C150 C157 C158 = CAP: Tolerance: 20; User Part Number: UPN; part number: CAP_SM-100UF,6.3V,20,E016591,C1206H71; tolerance: 20
C50 C55 C66 C67 C73 C78 C86 C87 C101 C105-C108 C159 C174 = CAP: Tolerance: 10; User Part Number: UPN; alternate symbols: C0402_ALT; part number: CAP_SM-4.7UF,6.3V,10,E020089,C0402; tolerance: 10
C51 C56-C59 C68-C70 C72 C74 C75 C88-C90 C93 C109-C116 C156 C160 C178 = CAP: Tolerance: 10; User Part Number: UPN; alternate symbols: C0402_ALT; part number: CAP_SM-0.47UF,10V,10,E007611,C0402; tolerance: 10
C81 = CAP: Tolerance: 10; User Part Number: UPN; part number: CAP_SM-0.22UF,16V,10,E000443,C0805; tolerance: 10
C123 C124 C131-C134 = CAP: User Part Number: UPN; Tolerance: 5; part number: CAP_SM-18PF,50V,5,E017960,C0201; tolerance: 5
C125 C128 C129 = CAP: User Part Number: UPN; Tolerance: 10; alternate symbols: (); part number: CAP_SM-0.001UF,25V,10,E006762,C0201; tolerance: 10
C126 = CAP: Tolerance: 10; User Part Number: UPN; alternate symbols: R0402_ALT; part number: CAP_SM-1UF,6.3V,10,E007449,C0402; tolerance: 10
C139 C155 = CAP: Tolerance: 10; User Part Number: UPN; alternate symbols: C0402_ALT; part number: CAP_SM-0.047UF,25V,10,E006454,C0402; tolerance: 10
C142 = CAP: Tolerance: 5; User Part Number: UPN; alternate symbols: C0402_ALT; part number: CAP_SM-150PF,50V,5,E012646,C0402; tolerance: 5
C143 = CAP: Tolerance: 5; User Part Number: UPN; alternate symbols: C0402_ALT; part number: CAP_SM-180PF,50V,5,E012612,C0402; tolerance: 5
C144 = CAP: Tolerance: 10; User Part Number: UPN; alternate symbols: C0402_ALT; part number: CAP_SM-0.0033UF,50V,10,E007461,C0402; tolerance: 10
C146 = CAP: Tolerance: 20; User Part Number: UPN; alternate symbols: (); part number: CAP_SM-22UF,6.3V,20,E006534,C0805H53; tolerance: 20
C147 = CAP: Tolerance: 10; User Part Number: UPN; alternate symbols: C0402_ALT; part number: CAP_SM-0.0056UF,25V,10,E011820,C0402; tolerance: 10
C165 = CAP: Tolerance: 10; User Part Number: UPN; alternate symbols: (); part number: CAP_SM-2.2UF,16V,10,E020871,C0603; tolerance: 10
C169 C170 = CAP: Tolerance: 10; User Part Number: UPN; alternate symbols: (); part number: CAP_SM-1UF,6.3V,10,E007449,C0402; tolerance: 10
C171 C172 = CAP: Tolerance: 10; User Part Number: UPN; alternate symbols: C0603L_ALT; part number: CAP_SM-2.2UF,16V,10,E020871,C0603; tolerance: 10
D1 D2 = DIO: Tolerance: N/A; User Part Number: UPN; alternate symbols: (); part number: DIO_SM-SESD0201X1UN-0020-09,9V,N/A,E022225,D0201; tolerance: N/A
D3 = DIO: Tolerance: N/A; User Part Number: UPN; alternate symbols: (); part number: DIO_SM-SMAJ5A,5V,N/A,E001108,DIOSMJ5_0; tolerance: N/A
DS1 DS2 = DIOLED: User Part Number: UPN; Tolerance: N/A; alternate symbols: LED0804_RA; part number: DIOLED_SM-LTST-S220TBKT,3.3V,N/A,E026167,LED0804; tolerance: N/A
E1-E6 = FERRITE: Tolerance: 25; User Part Number: UPN; alternate symbols: (); part number: FERRITE_SM-100OHM,25,E012241,L0805; tolerance: 25
F1 = FSFUSE: User Part Number: UPN; Tolerance: N/A; alternate symbols: (); part number: FSFUSE_SM-0.5A,6V,E023876,F0402H20; tolerance: N/A
GND GND#2 GND#4 UNK1V8#2 = -: Tolerance: N/A; User Part Number: UPN
GND#3 = -: User Part Number: UPN; Tolerance: N/A
L2 L3 = IND: User Part Number: UPN; Tolerance: 20; alternate symbols: (); part number: IND_SM-1.5UH,20,E017267,LSMSQ157H83; tolerance: 20
L4 = IND: User Part Number: UPN; Tolerance: 20; alternate symbols: (); part number: IND_SM-1UH,20,E015845,LSMSQ157H83; tolerance: 20
L5 = IND: User Part Number: UPN; Tolerance: 20; alternate symbols: (); part number: IND_SM-270NH,20,E027278,LSMSQ79H41; tolerance: 20
L6 = CHOKE4P: User Part Number: UPN; Tolerance: 25; alternate symbols: (); part number: CHOKE4P_SM-90OHMS AT 100MEGHZ,25,E027226,L0805-4PH39; tolerance: 25
L7 = CHOKE4P: User Part Number: UPN; Tolerance: N/A; alternate symbols: (); part number: CHOKE4P_SM-800OHMS AT 100MEGHZ,N/A,E027130,L2020_A; tolerance: N/A
L8 L9 = IND: Tolerance: 5; User Part Number: UPN; part number: IND_SM-330NH,5,E006599,L0805-F; tolerance: 5
L10P L12N L24N MIO0 MIO09-MIO11 MIO48 MIO49 MIO53 = NCWP: Tolerance: N/A; User Part Number: UPN; alternate symbols: (); part number: NCWP_TH-WP45,E002516,TPC75D45; tolerance: N/A
P1 = CN10P_ODD_EVEN: Tolerance: N/A; User Part Number: UPN; part number: CN10P_ODD_EVEN_TH-FTSH-105-01-L-D,E018623,CNHDR2X5H219; tolerance: N/A
P2 P3 = CN5P_3SHLD: User Part Number: UPN; Tolerance: N/A; alternate symbols: (); part number: CN5P_3SHLD_SM-47590-0001,E015753,CNMOLEX47590-0001; tolerance: N/A
Q1 Q2 Q4 = TRANNMOSFET_V8: User Part Number: UPN; Tolerance: N/A; part number: TRANNMOSFET_V8_SM-BSS138LT1G,E018770,SOT23; tolerance: N/A
Q3 = TRANTN0200T: User Part Number: UPN; Tolerance: N/A; alternate symbols: (); part number: TRANTN0200T_SM-SI2304DDS-T1-GE3,E014916,SOT23; tolerance: N/A
R1 R56 = RES: User Part Number: UPN; Tolerance: 1; part number: RES_SM-10,E013982,1/20W,1,R0201; tolerance: 1
R2 R53 = RES: Tolerance: 1; User Part Number: UPN; alternate symbols: R0402_ALT; part number: RES_SM-27.4K,E021819,1/10W,1,R0402; tolerance: 1
R3 R64 = RES: Tolerance: 1; User Part Number: UPN; alternate symbols: R0402_ALT; part number: RES_SM-46.4K,E011115,1/16W,1,R0402; tolerance: 1
R4 = RES: Tolerance: 1; User Part Number: UPN; alternate symbols: R0603_A; part number: RES_SM-17.8K,E011033,1/10W,1,R0603; tolerance: 1
R5 R10 R15 R43-R45 R85 R86 = RES: Tolerance: 1; User Part Number: UPN; alternate symbols: R0402_ALT; part number: RES_SM-0,E010661,1/16W,1,R0402; tolerance: 1
R6 R8 R60 R61 R67-R72 R74 R75 R221 R222 = RES: Tolerance: 1; User Part Number: UPN; alternate symbols: R0402_ALT; part number: RES_SM-10K,E003751,1/16W,1,R0402; tolerance: 1
R7 R42 = RES: Tolerance: 1; User Part Number: UPN; alternate symbols: R0402_ALT; part number: RES_SM-1K,E003763,1/10W,1,R0402; tolerance: 1
R9 = RES: User Part Number: UPN; Tolerance: 1; part number: RES_SM-10K,E004011,1/20W,1,R0201; tolerance: 1
R11 R46 R47 R54 R78-R81 R89 R91 = RES: Tolerance: 1; User Part Number: UPN; alternate symbols: R0402_ALT; part number: RES_SM-4.7K,E008190,1/16W,1,R0402; tolerance: 1
R12 R82 = RES: Tolerance: 5; User Part Number: UPN; alternate symbols: R0402_ALT; part number: RES_SM-39,E003441,1/16W,5,R0402; tolerance: 5
R13 R57 R76 R83 R84 R116 R119-R122 = RES: Tolerance: 1; User Part Number: UPN; alternate symbols: R0402_ALT; part number: RES_SM-20K,E003791,1/16W,1,R0402; tolerance: 1
R14 R40 R41 R66 R165 = RES: Tolerance: 1; User Part Number: UPN; alternate symbols: R0402_ALT; part number: RES_SM-240,E010877,1/16W,1,R0402; tolerance: 1
R16-R39 = RES: User Part Number: UPN; Tolerance: 1; part number: RES_SM-120,E011549,1/20W,1,R0201; tolerance: 1
R48 R87 = RES: Tolerance: 5; User Part Number: UPN; alternate symbols: R0402_ALT; part number: RES_SM-470,E017765,1/10W,5,R0402; tolerance: 5
R49 R63 = RES: User Part Number: UPN; Tolerance: 1; part number: RES_SM-14.3K,E014068,1/20W,1,R0201; tolerance: 1
R50 R59 = RES: Tolerance: 1; User Part Number: UPN; alternate symbols: R0402_ALT; part number: RES_SM-100K,E003796,1/16W,1,R0402; tolerance: 1
R51 R52 = RES: User Part Number: UPN; part number: RES_SM-1,E014056,1/20W,1,R0201
R55 R58 = RES: Tolerance: 1; User Part Number: UPN; alternate symbols: (); part number: RES_SM-1K,E023448,1/3W,1,R0805; tolerance: 1
R62 = RES: Tolerance: 1; User Part Number: UPN; alternate symbols: R0603L; part number: RES_SM-17.8K,E011033,1/10W,1,R0603; tolerance: 1
R65 = RES: Tolerance: 1; User Part Number: UPN; alternate symbols: R0402_ALT; part number: RES_SM-23.2K,E019517,1/16W,1,R0402; tolerance: 1
R73 = RES: Tolerance: 1; User Part Number: UPN; alternate symbols: (); part number: RES_SM-0.05,E013377,1/8W,1,R0805; tolerance: 1
R77 = RES: Tolerance: 1; User Part Number: UPN; alternate symbols: R0402_ALT; part number: RES_SM-8.06K,E021385,1/10W,1,R0402; tolerance: 1
R88 R90 = RES: Tolerance: 1; User Part Number: UPN; alternate symbols: (); part number: RES_SM-1K,E003763,1/10W,1,R0402; tolerance: 1
R142 = RES: Tolerance: 0.1; User Part Number: UPN; alternate symbols: R0402_ALT; part number: RES_SM-80.6,E022369,1/16W,0.1,R0402; tolerance: 0.1
RX1A TX1A = CNBNC5P: User Part Number: UPN; Tolerance: N/A; alternate symbols: (); part number: CNBNC5P_SM-JCCEM001,E027545,CNSMARAL687W375H171; tolerance: N/A
S1 = SWSPST5P_V2: User Part Number: UPN; Tolerance: N/A; alternate symbols: (); part number: SWSPST5P_V2_SM-PTS840 GKP SMTR LFS,E024294,SWSML140W138H55; tolerance: N/A
T1 T5 = XFMRTCMXXXX_V3: Tolerance: N/A; User Part Number: UPN; part number: XFMRTCMXXXX_V3_SM-TCM1-63AX+,E018203,TSML150W160H160; tolerance: N/A
U1 U7 = ADP1754: Tolerance: N/A; User Part Number: UPN; alternate symbols: (); part number: ADP1754_SM-ADP1754ACPZ-1.3,E022696,QFN16_4X4_PAD2_1X2_1; tolerance: N/A
U2 = ICMT41K256M16: User Part Number: UPN; Tolerance: N/A; alternate symbols: (); part number: ICMT41K256M16_SM-MT41K256M16TW-107 IT:P,E025601,FBGA96_C; tolerance: N/A
U3 = ADP2164: Tolerance: N/A; User Part Number: UPN; alternate symbols: (); part number: ADP2164_SM-ADP2164ACPZ,E013699,QFN16_4X4_PAD2_5X2_5; tolerance: N/A
U4 = ICXC7Z010: Tolerance: N/A; User Part Number: UPN; alternate symbols: (); part number: ICXC7Z010_SM-XC7Z010-1CLG225C,E025809,CSPBGA225; tolerance: N/A
U5 = AD9363: Tolerance: N/A; User Part Number: UPN; part number: AD9363_SM-AD9363ABCZ,E026056,BGA144-2; tolerance: N/A
U6 = ADP2114: User Part Number: UPN; Tolerance: N/A; alternate symbols: (); part number: ADP2114_SM-ADP2114ACPZ,E008105,QFN32_5X5_PAD3_1X3_1; tolerance: N/A
U8 U9 = ICNCP339: Tolerance: N/A; User Part Number: UPN; alternate symbols: (); part number: ICNCP339_SM-NCP339AFCT2G,E025896,WLCSP6; tolerance: N/A
U10 = ADM1177: Tolerance: N/A; User Part Number: UPN; alternate symbols: (); part number: ADM1177_SM-ADM1177-1ARMZ,E016506,RM10; tolerance: N/A
U11 = CMOSTCA9517: Tolerance: N/A; User Part Number: UPN; alternate symbols: (); part number: CMOSTCA9517_SM-TCA9517DGKR,E022173,MSOP8; tolerance: N/A
U12 = ADM7160_V2: User Part Number: UPN; Tolerance: N/A; alternate symbols: (); part number: ADM7160_V2_SM-ADM7160ACPZN1.8,E018693,DFN6_2X2_PAD1_6X1; tolerance: N/A
U13 = ICMT25Q: User Part Number: UPN; Tolerance: N/A; alternate symbols: (); part number: ICMT25Q_SM-MT25QU256ABA8E12-1SIT,E027529,TBGA24; tolerance: N/A
U14 = ICTPS51206: Tolerance: N/A; User Part Number: UPN; alternate symbols: (); part number: ICTPS51206_SM-TPS51206DSQR,E021346,SON10_2X2_PAD1_5X0_9; tolerance: N/A
U15 = ICUSB3320C: Tolerance: N/A; User Part Number: UPN; alternate symbols: (); part number: ICUSB3320C_SM-USB3320C-EZK,E021334,QFN32_5X5_PAD3_3X3_3; tolerance: N/A
U16 = ADP198: Tolerance: N/A; User Part Number: UPN; alternate symbols: (); part number: ADP198_SM-ADP198ACBZ-11,E024730,WLCSP4-2; tolerance: N/A
Y1 = XTALOSC4P_V7: Tolerance: N/A; User Part Number: UPN; alternate symbols: (); part number: XTALOSC4P_V7_SM-24MEGHZ,E022374,YSML98W79H35; tolerance: N/A
Y2 = XTALOSC4P_V7: Tolerance: N/A; User Part Number: UPN; part number: XTALOSC4P_V7_SM-33.333MEGHZ,E024048,YSML98W79H35; tolerance: N/A
Y3 = XTALOSC4P_V21: Tolerance: N/A; User Part Number: UPN; part number: XTALOSC4P_V21_SM-40MEGHZ,E020493,YSML126W98H47; tolerance: N/A

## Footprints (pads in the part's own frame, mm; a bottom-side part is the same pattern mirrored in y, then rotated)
BGA144-2
  round 0.356 smd: A1(-4.4,-4.4) A2(-4.4,-3.6) A3(-4.4,-2.8) A4(-4.4,-2) A5(-4.4,-1.2) A6(-4.4,-0.4) A7(-4.4,0.4) A8(-4.4,1.2) A9(-4.4,2) A10(-4.4,2.8) A11(-4.4,3.6) A12(-4.4,4.4) B1(-3.6,-4.4) B2(-3.6,-3.6) B3(-3.6,-2.8) B4(-3.6,-2) B5(-3.6,-1.2) B6(-3.6,-0.4) B7(-3.6,0.4) B8(-3.6,1.2) B9(-3.6,2) B10(-3.6,2.8) B11(-3.6,3.6) B12(-3.6,4.4) C1(-2.8,-4.4) C2(-2.8,-3.6) C3(-2.8,-2.8) C4(-2.8,-2) C5(-2.8,-1.2) C6(-2.8,-0.4) C7(-2.8,0.4) C8(-2.8,1.2) C9(-2.8,2) C10(-2.8,2.8) C11(-2.8,3.6) C12(-2.8,4.4) D1(-2,-4.4) D2(-2,-3.6) D3(-2,-2.8) D4(-2,-2) D5(-2,-1.2) D6(-2,-0.4) D7(-2,0.4) D8(-2,1.2) D9(-2,2) D10(-2,2.8) D11(-2,3.6) D12(-2,4.4) E1(-1.2,-4.4) E2(-1.2,-3.6) E3(-1.2,-2.8) E4(-1.2,-2) E5(-1.2,-1.2) E6(-1.2,-0.4) E7(-1.2,0.4) E8(-1.2,1.2) E9(-1.2,2) E10(-1.2,2.8) E11(-1.2,3.6) E12(-1.2,4.4) F1(-0.4,-4.4) F2(-0.4,-3.6) F3(-0.4,-2.8) F4(-0.4,-2) F5(-0.4,-1.2) F6(-0.4,-0.4) F7(-0.4,0.4) F8(-0.4,1.2) F9(-0.4,2) F10(-0.4,2.8) F11(-0.4,3.6) F12(-0.4,4.4) G1(0.4,-4.4) G2(0.4,-3.6) G3(0.4,-2.8) G4(0.4,-2) G5(0.4,-1.2) G6(0.4,-0.4) G7(0.4,0.4) G8(0.4,1.2) G9(0.4,2) G10(0.4,2.8) G11(0.4,3.6) G12(0.4,4.4) H1(1.2,-4.4) H2(1.2,-3.6) H3(1.2,-2.8) H4(1.2,-2) H5(1.2,-1.2) H6(1.2,-0.4) H7(1.2,0.4) H8(1.2,1.2) H9(1.2,2) H10(1.2,2.8) H11(1.2,3.6) H12(1.2,4.4) J1(2,-4.4) J2(2,-3.6) J3(2,-2.8) J4(2,-2) J5(2,-1.2) J6(2,-0.4) J7(2,0.4) J8(2,1.2) J9(2,2) J10(2,2.8) J11(2,3.6) J12(2,4.4) K1(2.8,-4.4) K2(2.8,-3.6) K3(2.8,-2.8) K4(2.8,-2) K5(2.8,-1.2) K6(2.8,-0.4) K7(2.8,0.4) K8(2.8,1.2) K9(2.8,2) K10(2.8,2.8) K11(2.8,3.6) K12(2.8,4.4) L1(3.6,-4.4) L2(3.6,-3.6) L3(3.6,-2.8) L4(3.6,-2) L5(3.6,-1.2) L6(3.6,-0.4) L7(3.6,0.4) L8(3.6,1.2) L9(3.6,2) L10(3.6,2.8) L11(3.6,3.6) L12(3.6,4.4) M1(4.4,-4.4) M2(4.4,-3.6) M3(4.4,-2.8) M4(4.4,-2) M5(4.4,-1.2) M6(4.4,-0.4) M7(4.4,0.4) M8(4.4,1.2) M9(4.4,2) M10(4.4,2.8) M11(4.4,3.6) M12(4.4,4.4)
C0201
  rect 0.305x0.406 smd: 1(-0.318,0) 2(0.318,0)
C0201#2
  rect 0.61x0.61 smd: 1(-0.495,0) 2(0.495,0)
C0402
  rect 0.61x0.61 smd: 1(-0.495,0) 2(0.495,0)
C0603
  rect 0.762x0.889 smd: 1(-0.699,0) 2(0.699,0)
C0603#2
  rect 1.092x1.194 smd: 1(-0.851,0) 2(0.851,0)
C0805
  rect 1.295x1.6 smd: 1(-0.953,0) 2(0.953,0)
C0805H53
  rect 1.295x1.6 smd: 1(-0.953,0) 2(0.953,0)
C0805H60
  rect 1.295x1.6 smd: 1(-0.953,0) 2(0.953,0)
C1206H71
  rect 1.6x2.007 smd: 1(-1.397,0) 2(1.397,0)
CNHDR1X1H344
  round 1.651 hole 1.143: 1(0,0)
CNHDR2X5H219
  rect 1.067x1.067 hole 0.711: 1(0,0)
  round 1.067 hole 0.711: 2(0,1.27) 3(1.27,0) 4(1.27,1.27) 5(2.54,0) 6(2.54,1.27) 7(3.81,0) 8(3.81,1.27) 9(5.08,0) 10(5.08,1.27)
CNMOLEX47590-0001
  oval 1.118x0.914 hole 0.864x0.66: (4.45,2.225) (4.45,-2.225)
  rect 1.346x0.406 smd: 1(4.123,-1.3) 2(4.123,-0.65) 3(4.123,0) 4(4.123,0.65) 5(4.123,1.3)
  custom 0.349x0.349 hole 1.295x0.61: SH1(1.45,4.175) SH3(1.45,-4.175)
  rect 1.905x2.896 smd: SH2(1.45,0)
CNSMARAL687W375H171
  rect 5.08x0.483 smd: 1(-0.254,0)
  rect 5.08x2.413 smd: 2(-0.254,4.381) 3(-0.254,4.381) 4(-0.254,-4.381) 5(-0.254,-4.381)
CSPBGA225
  round 0.305 smd: A1(-5.6,-5.6) A2(-5.6,-4.8) A3(-5.6,-4) A4(-5.6,-3.2) A5(-5.6,-2.4) A6(-5.6,-1.6) A7(-5.6,-0.8) A8(-5.6,0) A9(-5.6,0.8) A10(-5.6,1.6) A11(-5.6,2.4) A12(-5.6,3.2) A13(-5.6,4) A14(-5.6,4.8) A15(-5.6,5.6) B1(-4.8,-5.6) B2(-4.8,-4.8) B3(-4.8,-4) B4(-4.8,-3.2) B5(-4.8,-2.4) B6(-4.8,-1.6) B7(-4.8,-0.8) B8(-4.8,0) B9(-4.8,0.8) B10(-4.8,1.6) B11(-4.8,2.4) B12(-4.8,3.2) B13(-4.8,4) B14(-4.8,4.8) B15(-4.8,5.6) C1(-4,-5.6) C2(-4,-4.8) C3(-4,-4) C4(-4,-3.2) C5(-4,-2.4) C6(-4,-1.6) C7(-4,-0.8) C8(-4,0) C9(-4,0.8) C10(-4,1.6) C11(-4,2.4) C12(-4,3.2) C13(-4,4) C14(-4,4.8) C15(-4,5.6) D1(-3.2,-5.6) D2(-3.2,-4.8) D3(-3.2,-4) D4(-3.2,-3.2) D5(-3.2,-2.4) D6(-3.2,-1.6) D7(-3.2,-0.8) D8(-3.2,0) D9(-3.2,0.8) D10(-3.2,1.6) D11(-3.2,2.4) D12(-3.2,3.2) D13(-3.2,4) D14(-3.2,4.8) D15(-3.2,5.6) E1(-2.4,-5.6) E2(-2.4,-4.8) E3(-2.4,-4) E4(-2.4,-3.2) E5(-2.4,-2.4) E6(-2.4,-1.6) E7(-2.4,-0.8) E8(-2.4,0) E9(-2.4,0.8) E10(-2.4,1.6) E11(-2.4,2.4) E12(-2.4,3.2) E13(-2.4,4) E14(-2.4,4.8) E15(-2.4,5.6) F1(-1.6,-5.6) F2(-1.6,-4.8) F3(-1.6,-4) F4(-1.6,-3.2) F5(-1.6,-2.4) F6(-1.6,-1.6) F7(-1.6,-0.8) F8(-1.6,0) F9(-1.6,0.8) F10(-1.6,1.6) F11(-1.6,2.4) F12(-1.6,3.2) F13(-1.6,4) F14(-1.6,4.8) F15(-1.6,5.6) G1(-0.8,-5.6) G2(-0.8,-4.8) G3(-0.8,-4) G4(-0.8,-3.2) G5(-0.8,-2.4) G6(-0.8,-1.6) G7(-0.8,-0.8) G8(-0.8,0) G9(-0.8,0.8) G10(-0.8,1.6) G11(-0.8,2.4) G12(-0.8,3.2) G13(-0.8,4) G14(-0.8,4.8) G15(-0.8,5.6) H1(0,-5.6) H2(0,-4.8) H3(0,-4) H4(0,-3.2) H5(0,-2.4) H6(0,-1.6) H7(0,-0.8) H8(0,0) H9(0,0.8) H10(0,1.6) H11(0,2.4) H12(0,3.2) H13(0,4) H14(0,4.8) H15(0,5.6) J1(0.8,-5.6) J2(0.8,-4.8) J3(0.8,-4) J4(0.8,-3.2) J5(0.8,-2.4) J6(0.8,-1.6) J7(0.8,-0.8) J8(0.8,0) J9(0.8,0.8) J10(0.8,1.6) J11(0.8,2.4) J12(0.8,3.2) J13(0.8,4) J14(0.8,4.8) J15(0.8,5.6) K1(1.6,-5.6) K2(1.6,-4.8) K3(1.6,-4) K4(1.6,-3.2) K5(1.6,-2.4) K6(1.6,-1.6) K7(1.6,-0.8) K8(1.6,0) K9(1.6,0.8) K10(1.6,1.6) K11(1.6,2.4) K12(1.6,3.2) K13(1.6,4) K14(1.6,4.8) K15(1.6,5.6) L1(2.4,-5.6) L2(2.4,-4.8) L3(2.4,-4) L4(2.4,-3.2) L5(2.4,-2.4) L6(2.4,-1.6) L7(2.4,-0.8) L8(2.4,0) L9(2.4,0.8) L10(2.4,1.6) L11(2.4,2.4) L12(2.4,3.2) L13(2.4,4) L14(2.4,4.8) L15(2.4,5.6) M1(3.2,-5.6) M2(3.2,-4.8) M3(3.2,-4) M4(3.2,-3.2) M5(3.2,-2.4) M6(3.2,-1.6) M7(3.2,-0.8) M8(3.2,0) M9(3.2,0.8) M10(3.2,1.6) M11(3.2,2.4) M12(3.2,3.2) M13(3.2,4) M14(3.2,4.8) M15(3.2,5.6) N1(4,-5.6) N2(4,-4.8) N3(4,-4) N4(4,-3.2) N5(4,-2.4) N6(4,-1.6) N7(4,-0.8) N8(4,0) N9(4,0.8) N10(4,1.6) N11(4,2.4) N12(4,3.2) N13(4,4) N14(4,4.8) N15(4,5.6) P1(4.8,-5.6) P2(4.8,-4.8) P3(4.8,-4) P4(4.8,-3.2) P5(4.8,-2.4) P6(4.8,-1.6) P7(4.8,-0.8) P8(4.8,0) P9(4.8,0.8) P10(4.8,1.6) P11(4.8,2.4) P12(4.8,3.2) P13(4.8,4) P14(4.8,4.8) P15(4.8,5.6) R1(5.6,-5.6) R2(5.6,-4.8) R3(5.6,-4) R4(5.6,-3.2) R5(5.6,-2.4) R6(5.6,-1.6) R7(5.6,-0.8) R8(5.6,0) R9(5.6,0.8) R10(5.6,1.6) R11(5.6,2.4) R12(5.6,3.2) R13(5.6,4) R14(5.6,4.8) R15(5.6,5.6)
D0201
  rect 0.229x0.381 smd: A(0.22,0) C(-0.22,0)
DFN6_2X2_PAD1_6X1
  oval 0.305x0.864 smd: 1(-0.65,-1.082) 2(0,-1.082) 3(0.65,-1.082) 4(0.65,1.082) 5(0,1.082) 6(-0.65,1.082)
  rect 1.6x0.991 smd: PAD(0,0)
DIOSMJ5_0
  rect 2.286x1.88 smd: A(2.164,0) C(-2.164,0)
F0402H20
  rect 0.559x0.711 smd: 1(-0.49,0) 2(0.49,0)
FBGA96_C
  round 0.381 smd: A1(-6,-3.2) A2(-6,-2.4) A3(-6,-1.6) A7(-6,1.6) A8(-6,2.4) A9(-6,3.2) B1(-5.2,-3.2) B2(-5.2,-2.4) B3(-5.2,-1.6) B7(-5.2,1.6) B8(-5.2,2.4) B9(-5.2,3.2) C1(-4.4,-3.2) C2(-4.4,-2.4) C3(-4.4,-1.6) C7(-4.4,1.6) C8(-4.4,2.4) C9(-4.4,3.2) D1(-3.6,-3.2) D2(-3.6,-2.4) D3(-3.6,-1.6) D7(-3.6,1.6) D8(-3.6,2.4) D9(-3.6,3.2) E1(-2.8,-3.2) E2(-2.8,-2.4) E3(-2.8,-1.6) E7(-2.8,1.6) E8(-2.8,2.4) E9(-2.8,3.2) F1(-2,-3.2) F2(-2,-2.4) F3(-2,-1.6) F7(-2,1.6) F8(-2,2.4) F9(-2,3.2) G1(-1.2,-3.2) G2(-1.2,-2.4) G3(-1.2,-1.6) G7(-1.2,1.6) G8(-1.2,2.4) G9(-1.2,3.2) H1(-0.4,-3.2) H2(-0.4,-2.4) H3(-0.4,-1.6) H7(-0.4,1.6) H8(-0.4,2.4) H9(-0.4,3.2) J1(0.4,-3.2) J2(0.4,-2.4) J3(0.4,-1.6) J7(0.4,1.6) J8(0.4,2.4) J9(0.4,3.2) K1(1.2,-3.2) K2(1.2,-2.4) K3(1.2,-1.6) K7(1.2,1.6) K8(1.2,2.4) K9(1.2,3.2) L1(2,-3.2) L2(2,-2.4) L3(2,-1.6) L7(2,1.6) L8(2,2.4) L9(2,3.2) M1(2.8,-3.2) M2(2.8,-2.4) M3(2.8,-1.6) M7(2.8,1.6) M8(2.8,2.4) M9(2.8,3.2) N1(3.6,-3.2) N2(3.6,-2.4) N3(3.6,-1.6) N7(3.6,1.6) N8(3.6,2.4) N9(3.6,3.2) P1(4.4,-3.2) P2(4.4,-2.4) P3(4.4,-1.6) P7(4.4,1.6) P8(4.4,2.4) P9(4.4,3.2) R1(5.2,-3.2) R2(5.2,-2.4) R3(5.2,-1.6) R7(5.2,1.6) R8(5.2,2.4) R9(5.2,3.2) T1(6,-3.2) T2(6,-2.4) T3(6,-1.6) T7(6,1.6) T8(6,2.4) T9(6,3.2)
L0805
  rect 1.143x1.27 smd: 1(-0.953,0) 2(0.953,0)
L0805-4PH39
  rect 0.889x0.406 smd: 1(-0.845,-0.403) 2(0.845,-0.403) 3(0.845,0.403) 4(-0.845,0.403)
L0805-F
  rect 1.092x1.499 smd: 1(-1.046,0) 2(1.046,0)
L2020_A
  custom 0.425x0.425 smd: 1(-1.606,-1.501) 2(1.606,-1.501) 3(1.606,1.501) 4(-1.606,1.501)
LED0804
  rect 0.787x0.762 smd: A(1.1,0) C(-1.1,0)
LSMSQ79H41
  rect 1.041x2.21 smd: 1(-0.724,0) 2(0.724,0)
LSMSQ157H83
  rect 1.473x3.683 smd: 1(-1.232,0) 2(1.232,0)
MSOP8
  rect 0.305x1.321 smd: 1(-0.975,-2.3) 2(-0.325,-2.3) 3(0.325,-2.3) 4(0.975,-2.3) 5(0.975,2.3) 6(0.325,2.3) 7(-0.325,2.3) 8(-0.975,2.3)
QFN16_4X4_PAD2_1X2_1
  oval 0.356x1.041 smd: 1(-0.975,-1.9) 2(-0.325,-1.9) 3(0.325,-1.9) 4(0.975,-1.9) 9(0.975,1.9) 10(0.325,1.9) 11(-0.325,1.9) 12(-0.975,1.9)
  oval 1.041x0.356 smd: 5(1.9,-0.975) 6(1.9,-0.325) 7(1.9,0.325) 8(1.9,0.975) 13(-1.9,0.975) 14(-1.9,0.325) 15(-1.9,-0.325) 16(-1.9,-0.975)
  rect 2.108x2.108 smd: PAD(0,0)
QFN16_4X4_PAD2_5X2_5
  oval 0.356x0.991 smd: 1(-0.975,-1.974) 2(-0.325,-1.974) 3(0.325,-1.974) 4(0.975,-1.974) 9(0.975,1.974) 10(0.325,1.974) 11(-0.325,1.974) 12(-0.975,1.974)
  oval 0.991x0.356 smd: 5(1.974,-0.975) 6(1.974,-0.325) 7(1.974,0.325) 8(1.974,0.975) 13(-1.974,0.975) 14(-1.974,0.325) 15(-1.974,-0.325) 16(-1.974,-0.975)
  rect 2.489x2.489 smd: PAD(0,0)
QFN32_5X5_PAD3_1X3_1
  oval 0.305x0.889 smd: 1(-1.75,-2.45) 2(-1.25,-2.45) 3(-0.75,-2.45) 4(-0.25,-2.45) 5(0.25,-2.45) 6(0.75,-2.45) 7(1.25,-2.45) 8(1.75,-2.45) 17(1.75,2.45) 18(1.25,2.45) 19(0.75,2.45) 20(0.25,2.45) 21(-0.25,2.45) 22(-0.75,2.45) 23(-1.25,2.45) 24(-1.75,2.45)
  oval 0.889x0.305 smd: 9(2.45,-1.75) 10(2.45,-1.25) 11(2.45,-0.75) 12(2.45,-0.25) 13(2.45,0.25) 14(2.45,0.75) 15(2.45,1.25) 16(2.45,1.75) 25(-2.45,1.75) 26(-2.45,1.25) 27(-2.45,0.75) 28(-2.45,0.25) 29(-2.45,-0.25) 30(-2.45,-0.75) 31(-2.45,-1.25) 32(-2.45,-1.75)
  rect 3.099x3.099 smd: PAD(0,0)
QFN32_5X5_PAD3_3X3_3
  oval 0.305x0.889 smd: 1(-1.75,-2.45) 2(-1.25,-2.45) 3(-0.75,-2.45) 4(-0.25,-2.45) 5(0.25,-2.45) 6(0.75,-2.45) 7(1.25,-2.45) 8(1.75,-2.45) 17(1.75,2.45) 18(1.25,2.45) 19(0.75,2.45) 20(0.25,2.45) 21(-0.25,2.45) 22(-0.75,2.45) 23(-1.25,2.45) 24(-1.75,2.45)
  oval 0.889x0.305 smd: 9(2.45,-1.75) 10(2.45,-1.25) 11(2.45,-0.75) 12(2.45,-0.25) 13(2.45,0.25) 14(2.45,0.75) 15(2.45,1.25) 16(2.45,1.75) 25(-2.45,1.75) 26(-2.45,1.25) 27(-2.45,0.75) 28(-2.45,0.25) 29(-2.45,-0.25) 30(-2.45,-0.75) 31(-2.45,-1.25) 32(-2.45,-1.75)
  rect 3.302x3.302 smd: PAD(0,0)
R0201
  rect 0.305x0.406 smd: 1(-0.318,0) 2(0.318,0)
R0402
  rect 0.61x0.61 smd: 1(-0.495,0) 2(0.495,0)
R0603
  rect 0.889x0.813 smd: 1(-0.737,0) 2(0.737,0)
R0603#2
  rect 0.711x0.914 smd: 1(-0.6,0) 2(0.6,0)
R0805
  rect 1.295x1.397 smd: 1(-0.953,0) 2(0.953,0)
RM10
  rect 0.305x1.321 smd: 1(-1,-2.171) 2(-0.5,-2.171) 3(0,-2.171) 4(0.5,-2.171) 5(1,-2.171) 6(1,2.171) 7(0.5,2.171) 8(0,2.171) 9(-0.5,2.171) 10(-1,2.171)
SON10_2X2_PAD1_5X0_9
  oval 0.203x0.762 smd: 1(-0.8,-1) 2(-0.4,-1) 3(0,-1) 4(0.4,-1) 5(0.8,-1) 6(0.8,1) 7(0.4,1) 8(0,1) 9(-0.4,1) 10(-0.8,1)
  rect 1.499x0.889 smd: PAD(0,0)
SOT23
  rect 1.016x1.397 smd: 1(-0.94,-1.118) 2(0.94,-1.118) 3(0,1.118)
SWSML140W138H55
  round 0.889 hole 0.711 unplated: (-0.9,0) (0.9,0)
  rect 1.041x1.397 smd: 1(-0.721,-1.799) 2(-0.721,1.799) 3(0.721,-1.799) 4(0.721,1.799)
  rect 0.508x1.092 smd: 5(-1.704,0)
TBGA24
  round 0.33 smd: A2(-2,-1) A3(-2,0) A4(-2,1) A5(-2,2) B1(-1,-2) B2(-1,-1) B3(-1,0) B4(-1,1) B5(-1,2) C1(0,-2) C2(0,-1) C3(0,0) C4(0,1) C5(0,2) D1(1,-2) D2(1,-1) D3(1,0) D4(1,1) D5(1,2) E1(2,-2) E2(2,-1) E3(2,0) E4(2,1) E5(2,2)
TPC75D45
  round 1.905 hole 1.143: 1(0,0)
TPSMC40
  round 1.016 hole 0.508: 1(0,0)
TSML150W160H160
  rect 0.762x1.651 smd: 1(-1.27,1.587) 2(0,1.587) 3(1.27,1.587) 4(1.27,-1.587) 5(0,-1.587) 6(-1.27,-1.587)
unnamed
  round 1.016 smd: (0,0)
unnamed#3
  round 1.905 hole 1.143: 1(0,0)
WLCSP4-2
  round 0.254 smd: A1(-0.25,-0.25) A2(-0.25,0.25) B1(0.25,-0.25) B2(0.25,0.25)
WLCSP6
  round 0.254 smd: A1(-0.5,-0.25) A2(-0.5,0.25) B1(0,-0.25) B2(0,0.25) C1(0.5,-0.25) C2(0.5,0.25)
YSML98W79H35
  rect 1.092x0.991 smd: 1(-0.921,-0.72) 2(0.921,-0.72) 3(0.921,0.72) 4(-0.921,0.72)
YSML126W98H47
  rect 1.397x1.194 smd: 1(-1.2,-0.95) 2(1.2,-0.95) 3(1.2,0.95) 4(-1.2,0.95)

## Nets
1V8: C1.1 C10.1 C22.1 C25.1 C46.1 C48.1 C49.1 C50.1 C51.1 C52.1 C53.1 C65.1 C67.1 C69.1 C76.1 C77.1 C78.1 C82.1 C83.1 C90.1 C103.1 C104.1 C105.1 C106.1 C107.1 C108.1 C109.1 C110.1 C111.1 C112.1 C113.1 C114.1 C115.1 C116.1 C117.1 C118.1 C119.1 C120.1 C140.1 C149.1 C150.1 C152.1 C153.1 C154.1 C158.1 C159.1 C160.1 C161.1 C162.1 C163.2(N2) C166.2(N2) C168.1 C174.1 E1.1 E4.1 E5.1 L5.2(N2) P1.10(N5) R8.1 R11.1 R13.1 R14.1 R44.1 R45.1 R46.2(N2) R47.2(N2) R50.2(N2) R57.1 R64.2(N2) R74.1 R76.1 R78.1 R79.1 R83.1 R84.2(N2) R122.2(N2) U1.1 U1.2 U1.3 U1.15 U1.16 U4.A6 U4.B13 U4.C10 U4.D7 U4.E14 U4.F11 U4.G4 U4.H4 U4.H9 U4.H15 U4.J4 U4.J6 U4.J8 U4.J12 U4.K8 U4.K9 U4.L6 U4.M13 U4.N10 U4.P7 U4.R14 U7.1 U7.2 U7.3 U7.15 U7.16 U11.1 U13.B4 U15.8 U15.11 U15.14 U15.28 U15.30 U15.32 UNK1V8.1 UNK1V8#2.1 Y1.4(VDD) Y2.4(VDD)
1V35: C54.1 C55.1 C56.1 C57.1 C58.1 C59.1 C60.1 C61.1 C86.1 C87.1 C88.1 C89.1 C91.1 C92.1 C94.1 C95.1 C96.1 C97.1 C100.1 C145.1 C148.1 C151.1 L2.2(N2) R41.2(N2) R62.1 U2.A1 U2.A8 U2.B2 U2.C1 U2.C9 U2.D2 U2.D9 U2.E9 U2.F1 U2.G7 U2.H2 U2.H9 U2.K2 U2.K8 U2.N1 U2.N9 U2.R1 U2.R9 U4.B3 U4.E4 U4.F1 U4.J2 U4.M3 U4.R4 U14.1 UNK1V35.1
